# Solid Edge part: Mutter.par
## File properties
Sűrűség: 0,000 kg/m^3
Pontosság: 0,990
Author: ahadarics
Last saved by: psaghy
Revision: 77
Username: ahadarics
Dokumentum tartalom típus: 0
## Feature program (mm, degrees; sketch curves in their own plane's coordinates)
base feature "unnamed BaseFeature 1"
sketch for "Furat_1" plane through (9, 0, 0) normal (1, 0, 0) x-axis (0, 1, 0)
hole "Furat_1" through  StartChamferOffset = 0.47 mm; StartChamferAngle = 45 deg
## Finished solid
Body 1: solid body, 23 faces, 47 edges, 26 vertices.
  Faces by surface: cone 14, plane 8, cylinder 1
  Edges by curve: spline 24, circle 16, line 7
Bounding box of the edges (mm): 9.000 x 34.641 x 30.000, from (0, -17.3205, -15) to (9, 17.3205, 15).
Cylindrical faces by radius (mm): R9.188 x1
Conical faces (half-angle, radius in mm at the cone's reference point): 45 deg R9.658 x1, 60 deg R9.5939 x1, 60 deg R16.1603 x12
Planar faces by outward normal: +x 1, +z 1, -x 1, -z 1, oblique 4
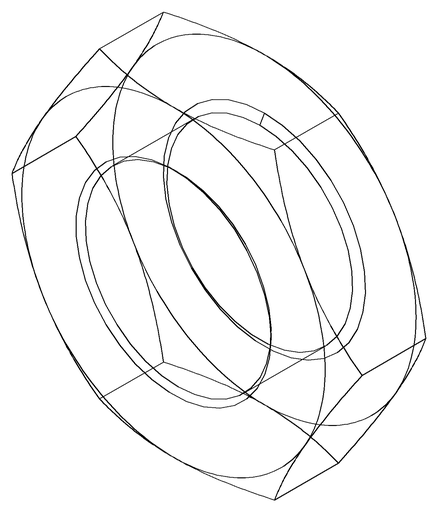
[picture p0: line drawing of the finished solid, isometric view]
